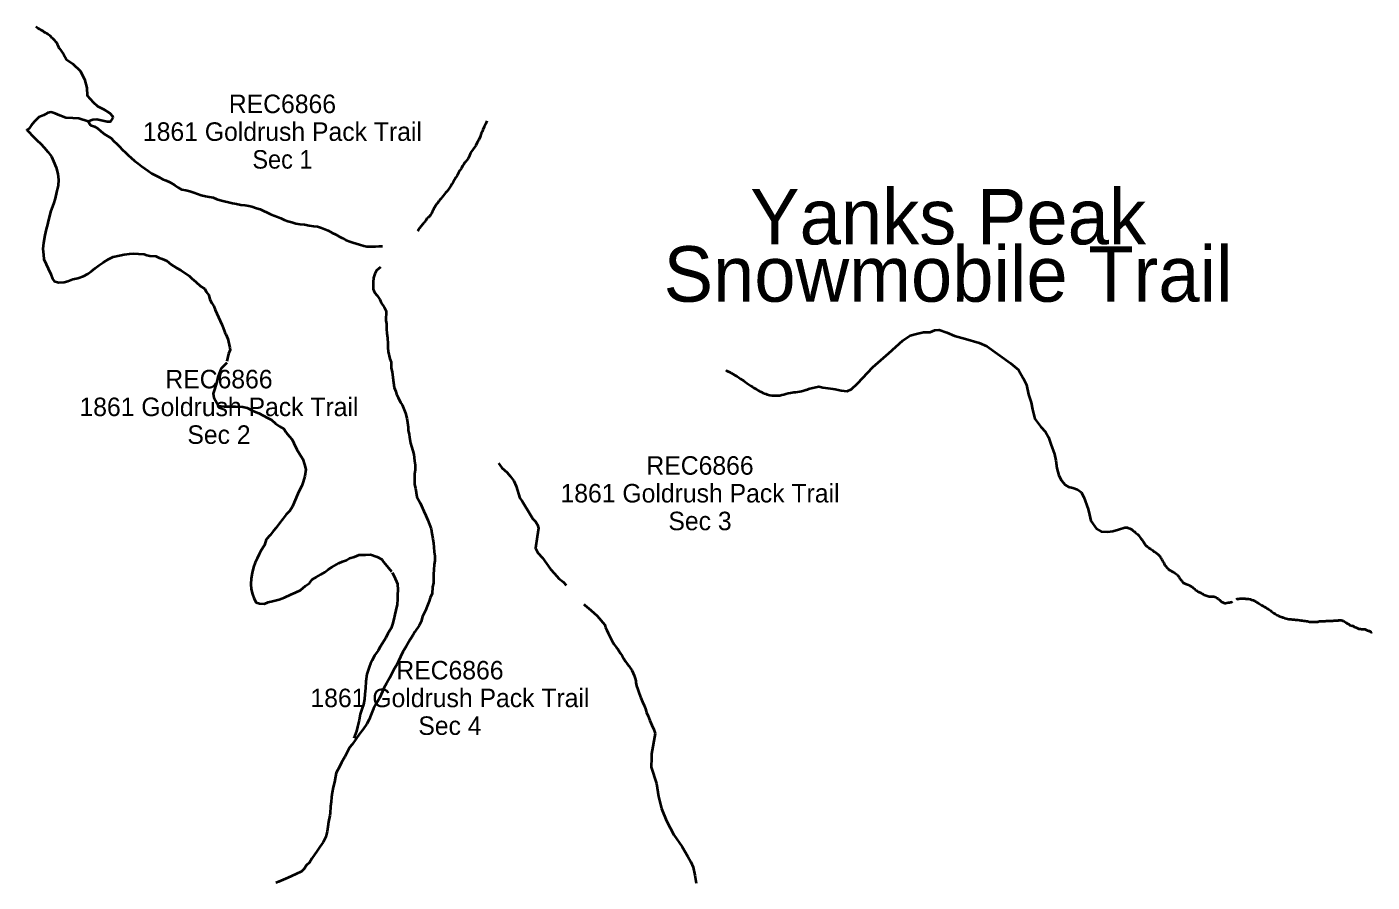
# Model space of a CAD drawing. Extents: x 322505 to 642419, y 5806860 to 5919753.
# Drawn here: x 597056 to 604330, y 5876927 to 5881551 of the extents above; entities that cross this region are included whole.
import ezdxf
from ezdxf.enums import TextEntityAlignment as Align

# ---------------------------------------------------------------- set-up
doc = ezdxf.new("R2010")
doc.units = 0
doc.header["$LTSCALE"] = 140
doc.layers.add('4', color=7, linetype='Continuous', lineweight=40)
doc.layers.add('5', color=7, linetype='Continuous', lineweight=40)

msp = doc.modelspace()

# ---------------------------------------------------------------- linework, layer by layer
at = {"layer": '4'}
for points in [[(599543.3, 5881042.4), (599537, 5881028), (599537, 5881027), (599529, 5881011), (599522, 5880994), (599517, 5880983)], [(599543.3, 5881042.4), (599537, 5881028), (599537, 5881027), (599529, 5881011), (599522, 5880994), (599517, 5880983)], [(599517, 5880983), (599513, 5880974), (599506, 5880957), (599499, 5880940), (599491, 5880925), (599484, 5880910), (599454, 5880870)], [(599517, 5880983), (599513, 5880974), (599506, 5880957), (599499, 5880940), (599491, 5880925), (599484, 5880910), (599454, 5880870)], [(599454, 5880870), (599447, 5880850), (599441, 5880840), (599434, 5880831), (599429, 5880823), (599424, 5880817), (599419, 5880809), (599412, 5880799), (599405, 5880787), (599397, 5880774), (599390, 5880761), (599382, 5880748), (599375, 5880736), (599368, 5880723), (599361, 5880712), (599354, 5880701), (599348, 5880691), (599340, 5880680), (599333, 5880670), (599326, 5880661), (599320, 5880653), (599314, 5880646), (599307, 5880637), (599300, 5880628), (599292, 5880619), (599284, 5880609), (599277, 5880600), (599271, 5880592), (599265, 5880583), (599260, 5880575), (599255, 5880566), (599252, 5880559), (599248, 5880550), (599243, 5880542), (599239, 5880534), (599235, 5880528), (599232, 5880525), (599230, 5880523), (599226, 5880520), (599223, 5880517), (599219, 5880515)], [(599454, 5880870), (599447, 5880850), (599441, 5880840), (599434, 5880831), (599429, 5880823), (599424, 5880817), (599419, 5880809), (599412, 5880799), (599405, 5880787), (599397, 5880774), (599390, 5880761), (599382, 5880748), (599375, 5880736), (599368, 5880723), (599361, 5880712), (599354, 5880701), (599348, 5880691), (599340, 5880680), (599333, 5880670), (599326, 5880661), (599320, 5880653), (599314, 5880646), (599307, 5880637), (599300, 5880628), (599292, 5880619), (599284, 5880609), (599277, 5880600), (599271, 5880592), (599265, 5880583), (599260, 5880575), (599255, 5880566), (599252, 5880559), (599248, 5880550), (599243, 5880542), (599239, 5880534), (599235, 5880528), (599232, 5880525), (599230, 5880523), (599226, 5880520), (599223, 5880517), (599219, 5880515)], [(599219, 5880515), (599217, 5880511), (599215, 5880508), (599213, 5880504), (599211, 5880501), (599208, 5880499), (599205, 5880494), (599200, 5880489), (599196, 5880484), (599192, 5880479), (599188, 5880474), (599184, 5880469), (599181, 5880465), (599177, 5880460), (599173, 5880455), (599169, 5880448), (599167.3, 5880445.9)], [(599219, 5880515), (599217, 5880511), (599215, 5880508), (599213, 5880504), (599211, 5880501), (599208, 5880499), (599205, 5880494), (599200, 5880489), (599196, 5880484), (599192, 5880479), (599188, 5880474), (599184, 5880469), (599181, 5880465), (599177, 5880460), (599173, 5880455), (599169, 5880448), (599167.3, 5880445.9)], [(598968.2, 5880252.5), (598946.2, 5880234.4), (598937.3, 5880216), (598930.3, 5880193.6), (598928.5, 5880171.2), (598927.4, 5880139.5), (598928.5, 5880132.2), (598934.7, 5880115.5), (598950.5, 5880098.3), (598963.4, 5880077), (598972.2, 5880058.8), (598988.1, 5880036), (598988.1, 5880036), (598995.4, 5880021.3), (598997.5, 5880013), (598996.4, 5879963), (598996.4, 5879963), (598999.6, 5879945), (598999.6, 5879934.5), (598999.6, 5879916.7), (599001.7, 5879894.8), (599004.9, 5879869.7), (599008.2, 5879836.6), (599008, 5879815.3), (599010.1, 5879795.1), (599018.5, 5879756.4), (599024.7, 5879737.6), (599024.7, 5879716.7), (599025.8, 5879705.2), (599030, 5879685.3), (599035.2, 5879655), (599042.5, 5879601.6), (599049.8, 5879579.7), (599055.1, 5879565), (599063.4, 5879547.2), (599076, 5879520), (599084.9, 5879507.5), (599084.9, 5879507.5), (599091.7, 5879489.7), (599103.1, 5879462), (599109.5, 5879434.8), (599113.7, 5879412.8), (599117.9, 5879387.2), (599117.9, 5879370.5), (599123.1, 5879346.9), (599124.1, 5879332.3), (599130.4, 5879300.1), (599134.6, 5879281.3), (599141.9, 5879258.3), (599147.2, 5879238.4), (599151.3, 5879204.9), (599155.5, 5879183), (599154.5, 5879155.8), (599151.3, 5879131.7), (599152.4, 5879103.5), (599152.4, 5879077.3), (599156.6, 5879057.5), (599164.9, 5879010.4), (599181.7, 5878978), (599189.8, 5878961.2), (599201.8, 5878931.9), (599213.7, 5878909.1), (599223.6, 5878883.8), (599232.4, 5878860.5), (599241.3, 5878836.2), (599246.1, 5878812.4), (599249.9, 5878783.4), (599254.7, 5878760.1), (599256.9, 5878737.8), (599258.6, 5878713.4), (599260.9, 5878691.6), (599261.6, 5878664.1), (599257.8, 5878644.8), (599255.7, 5878615.5), (599254.7, 5878592.5), (599253.6, 5878574.7), (599253.6, 5878544.4), (599248.1, 5878522.5), (599246.7, 5878487.2), (599237.2, 5878464.2), (599230.4, 5878446.6), (599221, 5878419.4), (599211.5, 5878396.4), (599195.2, 5878363.8), (599188.4, 5878336.7), (599177.5, 5878313.7), (599153.1, 5878281.1), (599143.6, 5878264.9), (599128.7, 5878239.1), (599107, 5878201.1), (599089.4, 5878171.3), (599075.8, 5878144.2), (599065, 5878122.5), (599058.2, 5878106.2), (599040.5, 5878076.4), (599016.1, 5878028.9), (598999.8, 5878001.8), (598987.6, 5877978.8), (598978.1, 5877958.4), (598962.7, 5877922.3), (598946.7, 5877895.2)], [(599605.4, 5879192.5), (599615.4, 5879178.8), (599623.8, 5879166.4), (599637.4, 5879153.5), (599652.1, 5879140.9), (599668.8, 5879121.8), (599689.2, 5879097.1), (599701.7, 5879068), (599720.8, 5879002.9), (599733, 5878986.5), (599750.6, 5878959.5), (599764.2, 5878936.4), (599791.8, 5878890.5), (599806.8, 5878876.4), (599817.2, 5878858.4), (599821.7, 5878841.4), (599815.5, 5878793.3), (599806.2, 5878732.6), (599818.8, 5878708), (599843.6, 5878680.8), (599887.4, 5878618.6), (599908.1, 5878595.7), (599932.8, 5878567.9), (599956, 5878550.5), (599971.3, 5878533)], [(600067.9, 5878429.4), (600073.2, 5878423.8), (600106, 5878396.8), (600139.5, 5878367.4), (600180, 5878318), (600185, 5878304), (600191, 5878290), (600198, 5878273), (600209, 5878251), (600221, 5878230), (600232, 5878212), (600242, 5878197), (600251, 5878186), (600257, 5878177), (600265, 5878164), (600274, 5878150), (600284, 5878134), (600293, 5878120), (600301, 5878108), (600310, 5878097), (600318, 5878086), (600326, 5878073), (600334, 5878057), (600340, 5878045), (600344, 5878033), (600346, 5878023), (600348, 5878014), (600349, 5878006), (600353, 5877989), (600359, 5877968), (600367, 5877946), (600376, 5877923), (600385, 5877901), (600393, 5877882), (600400, 5877864), (600407, 5877845), (600415, 5877825), (600425, 5877801), (600435, 5877775), (600445, 5877752), (600453, 5877731)], [(598946.7, 5877895.2), (598929.7, 5877866.6), (598915.3, 5877829.9), (598906.6, 5877806), (598893.8, 5877783.5), (598874.8, 5877753.3), (598854.2, 5877728.8), (598814.4, 5877670.4), (598800.8, 5877655.1), (598790.8, 5877637.1), (598775.2, 5877603.9), (598757.5, 5877574.3), (598747.2, 5877554.4), (598728, 5877518.2), (598724.5, 5877497.9), (598719.8, 5877466.9), (598711.4, 5877439.7), (598706.7, 5877411.5), (598702.9, 5877387.1), (598700.1, 5877360.8), (598698.2, 5877335.4), (598696.3, 5877300.7), (598693.5, 5877286.6), (598686.6, 5877253.8), (598683.8, 5877225.8), (598679.9, 5877200.9), (598671.6, 5877171.9), (598657.6, 5877142.3), (598640, 5877117.7), (598624.4, 5877096.8), (598596.9, 5877054.9), (598583.8, 5877033.4), (598566.7, 5877018), (598554.4, 5876999.1), (598540.7, 5876985.3), (598510.4, 5876969.8), (598467.5, 5876951), (598416.2, 5876929), (598402.6, 5876922.8)], [(600453, 5877731), (600433.1, 5877620.4), (600433.6, 5877599.9), (600431.6, 5877549.2), (600460.8, 5877460.2), (600471.7, 5877390.4), (600487.8, 5877324.3), (600514.8, 5877257.8), (600553.5, 5877182.2), (600599.4, 5877118.8), (600629.7, 5877065.1), (600645.8, 5877037.6), (600658, 5877007.1), (600666.8, 5876964), (600675, 5876920.9)]]:
    msp.add_lwpolyline(points, dxfattribs=at)
at = {"layer": '5'}
for points in [[(597231.7, 5881433), (597254.4, 5881402.8), (597270.1, 5881374.7), (597303.8, 5881350), (597343.1, 5881312.9), (597367.8, 5881268), (597379, 5881220.9), (597381.3, 5881179.3), (597413.9, 5881144.5), (597437.4, 5881122), (597470, 5881105.2), (597504.8, 5881083.9), (597518.3, 5881068.1), (597519.6, 5881059.4)], [(597519.6, 5881059.4), (597505.6, 5881037), (597488.9, 5881037), (597434.4, 5881050.3), (597412.7, 5881048.9), (597386.9, 5881038.4), (597337.2, 5881054.5), (597304.4, 5881058), (597266, 5881059.4), (597234.5, 5881071.3), (597208, 5881083.1), (597187, 5881089.4), (597169.5, 5881085.2), (597146.5, 5881074), (597120.6, 5881062.2), (597095.5, 5881037), (597078, 5881017.5), (597067.5, 5881002.1), (597055.6, 5880993.7), (597058.4, 5880990.2), (597093.4, 5880953.9), (597110.1, 5880937.8), (597131.1, 5880919), (597148.6, 5880899.4), (597168.1, 5880874.9), (597188, 5880850.7), (597200.2, 5880824.3), (597213.6, 5880790.9), (597222.5, 5880756.4), (597226.1, 5880723.2), (597224.7, 5880692.7), (597216, 5880657.4), (597208.4, 5880623.6), (597200.3, 5880593.2), (597190.5, 5880570.9), (597182.8, 5880549.9), (597174.4, 5880513.6), (597170.9, 5880499.6), (597166.4, 5880481.5), (597159.4, 5880456.3), (597152.4, 5880424.2), (597144.5, 5880383), (597141.8, 5880351.3), (597144.5, 5880318.6), (597148, 5880294.1), (597159.8, 5880268.3), (597170.7, 5880244.9), (597184.4, 5880213), (597193.3, 5880188), (597202.4, 5880176.1), (597225.7, 5880169.3), (597256.9, 5880170.5), (597277.1, 5880176.8), (597304.4, 5880186.3), (597331.2, 5880192.6), (597361.9, 5880203.6), (597385.6, 5880215.2), (597405, 5880230.5), (597425.2, 5880246), (597445.7, 5880261.6), (597468.3, 5880276.8), (597496.2, 5880294.7), (597522.9, 5880308.1), (597556.7, 5880314.2), (597582.4, 5880320.1), (597609.8, 5880323.5), (597633.7, 5880324.7), (597659.5, 5880322.9), (597689, 5880322.7), (597704.4, 5880317.3), (597721.2, 5880313.1), (597752, 5880311.7), (597770.8, 5880301.9), (597787.6, 5880296.3), (597811.4, 5880285.2), (597835.1, 5880265.6), (597864.5, 5880248.8), (597888.2, 5880236.2), (597933.5, 5880204.8), (597947.9, 5880189.7), (597968.4, 5880172.5), (597995.2, 5880149.7), (598018.2, 5880133.8), (598025.2, 5880117.5), (598039.2, 5880099.7), (598044.7, 5880077.3), (598055.1, 5880057.8)], [(597386.9, 5881038.4), (597400.1, 5881019.6), (597400.1, 5881019.6), (597420.7, 5881012.1), (597439.4, 5881000.9), (597456.2, 5880986), (597474.9, 5880971), (597493.6, 5880959.8), (597510.5, 5880948.6), (597510.5, 5880948.6), (597525.4, 5880933.6), (597542.3, 5880918.6), (597557.2, 5880903.7), (597572.2, 5880886.8), (597589, 5880871.9), (597604, 5880856.9), (597619, 5880842), (597637.7, 5880827), (597656.4, 5880812), (597675.1, 5880797.1), (597693.8, 5880785.9), (597710.6, 5880772.8), (597731.2, 5880757.8), (597749.9, 5880748.5), (597770.5, 5880739.1), (597789.2, 5880727.9), (597807.9, 5880720.4), (597828.5, 5880711.1), (597854.7, 5880694.2), (597873.4, 5880683), (597892.1, 5880671.8), (597892.1, 5880671.8), (597914.5, 5880668), (597937, 5880662.4), (597957.5, 5880655), (597978.1, 5880647.5), (597998.7, 5880640), (597998.7, 5880640), (598021.1, 5880636.3), (598041.7, 5880632.5), (598063.4, 5880627.4), (598083, 5880619.6), (598100.8, 5880613.7), (598122.2, 5880608.2), (598146.5, 5880602.6), (598167.1, 5880597), (598189.5, 5880593.2), (598211.9, 5880589.5), (598234.4, 5880587.6), (598255, 5880583.9), (598255, 5880583.9), (598271.9, 5880579.2), (598297.5, 5880571.4), (598316.2, 5880564.5), (598335.4, 5880555.8), (598354.1, 5880546.5), (598372.8, 5880539), (598391.5, 5880531.5), (598410.2, 5880524), (598428.9, 5880516.6), (598447.6, 5880507.2), (598466.3, 5880499.7), (598488.8, 5880494.1), (598509.4, 5880488.5), (598531.8, 5880484.8), (598556.1, 5880482.9), (598582.3, 5880477.3), (598604.8, 5880473.6), (598627.2, 5880471.7), (598627.2, 5880471.7), (598647.8, 5880464.2), (598666.5, 5880456.7), (598685.2, 5880449.2), (598705.8, 5880438), (598705.8, 5880438), (598726.4, 5880428.7), (598745.1, 5880417.4), (598762.5, 5880408.1), (598779.3, 5880400.2), (598797, 5880392.4), (598817.6, 5880384.5), (598854, 5880373.7), (598877.6, 5880366.8), (598894.4, 5880363.9), (598913.5, 5880363.8), (598940.1, 5880364.2), (598959.6, 5880364.9), (598978.3, 5880365.4)], [(598055.1, 5880057.8), (598067, 5880040.2), (598067, 5880040.2), (598074.3, 5880020.3), (598083.3, 5880001.2), (598091.5, 5879982.1), (598100.6, 5879962.2), (598109.7, 5879942.2), (598117.8, 5879923.1), (598123.8, 5879903.4), (598125.4, 5879899.3)], [(598125.4, 5879899.3), (598131.4, 5879888.7), (598142.6, 5879864.9), (598153.8, 5879815.7), (598155.1, 5879804.2), (598146.2, 5879783.2), (598137, 5879743.4)], [(600835, 5879694), (600840, 5879692), (600847, 5879688), (600854, 5879685), (600860, 5879682), (600866, 5879678), (600874, 5879673), (600884, 5879668), (600895, 5879662), (600905, 5879655), (600915, 5879648), (600924, 5879643), (600932, 5879637), (600940, 5879631), (600949, 5879625), (600960, 5879618), (600970, 5879611), (600979, 5879605), (600987, 5879600), (600994, 5879595), (601002, 5879590), (601009, 5879586), (601018, 5879582), (601027, 5879578), (601036, 5879573), (601045, 5879569), (601052, 5879566), (601059, 5879563), (601066, 5879561), (601074, 5879559), (601084, 5879558), (601095, 5879558), (601105, 5879557), (601113, 5879557), (601121, 5879558), (601128, 5879558), (601138, 5879561), (601149, 5879563), (601160, 5879567), (601172, 5879570), (601184, 5879573), (601194, 5879574), (601203, 5879575), (601214, 5879576), (601224, 5879578), (601236, 5879580), (601244, 5879581), (601251, 5879583), (601257, 5879585), (601263, 5879587), (601269, 5879589), (601273, 5879590), (601276, 5879591), (601280, 5879592), (601284, 5879594), (601289, 5879596), (601339, 5879606), (601360, 5879602), (601414, 5879594), (601426, 5879592), (601458, 5879585), (601492, 5879581), (601514, 5879592), (601548, 5879623), (601631, 5879711), (601717, 5879786), (601793, 5879855), (601832, 5879882), (601866, 5879892), (601904, 5879901), (601941, 5879901), (601965, 5879911), (601988, 5879913), (602031, 5879899), (602072, 5879880), (602132, 5879865), (602206, 5879843), (602247, 5879825), (602374, 5879732), (602417, 5879696), (602443, 5879651), (602462, 5879615), (602472, 5879563), (602486, 5879520), (602493, 5879482), (602507, 5879431), (602539, 5879388), (602564, 5879361), (602580, 5879332), (602592, 5879294), (602612, 5879240), (602620, 5879207), (602625, 5879165), (602636, 5879126), (602650, 5879099), (602671, 5879075), (602689, 5879064), (602712, 5879058), (602737, 5879049), (602757, 5879036), (602771, 5879008)], [(598137, 5879735), (598127.2, 5879725.2), (598110.4, 5879707.1), (598100.6, 5879691.7), (598088.1, 5879656.8), (598082.5, 5879631.6), (598072.7, 5879595.3), (598063.6, 5879568.8), (598067, 5879547.6), (598074.6, 5879530.8), (598090.9, 5879502.4), (598121.6, 5879498.2), (598144, 5879498.2), (598184.5, 5879498.2), (598223.6, 5879496.8), (598246, 5879491.2), (598278.1, 5879475.8), (598310.3, 5879463.2), (598332.6, 5879449.3), (598356.4, 5879436.7), (598378.8, 5879425.5), (598399.7, 5879406), (598423.5, 5879390.6), (598444.4, 5879377.3), (598458.4, 5879357.8), (598473.8, 5879338.2), (598489.2, 5879320), (598498.9, 5879300.5), (598515.7, 5879265.5), (598529.7, 5879241.8), (598547.9, 5879213.8), (598556.2, 5879184.5), (598563.2, 5879158.1), (598559.3, 5879122), (598549, 5879090.7), (598541.8, 5879070), (598523.7, 5879035.6), (598511.4, 5879003.8), (598500.3, 5878979.1), (598491.1, 5878958.6), (598476.9, 5878934.8), (598458.4, 5878914.1), (598441.6, 5878893.2), (598420.7, 5878868), (598401.1, 5878841.5), (598388.5, 5878826.1), (598370.4, 5878802.4), (598349.4, 5878778.6), (598339.6, 5878749.1), (598320.8, 5878718.6), (598312, 5878700.2), (598300.4, 5878677), (598289.3, 5878655.7), (598280.3, 5878630.5), (598273.2, 5878600), (598268.6, 5878567.9), (598266.9, 5878538.1), (598269.1, 5878510.2), (598275.1, 5878483.2), (598283.9, 5878458.5), (598295.3, 5878438.7), (598313, 5878432.6), (598341, 5878432.1), (598360.6, 5878440.5), (598382.9, 5878446.1), (598419.3, 5878455.9), (598448.6, 5878465.7), (598483.6, 5878482.4), (598508, 5878493.6), (598534.6, 5878504.8), (598562.5, 5878528.5), (598583.5, 5878542.5), (598599, 5878563.3), (598620, 5878575.3), (598645, 5878590), (598665.9, 5878602.6), (598685.5, 5878616.5), (598703.7, 5878629.1), (598742, 5878652.2), (598762.2, 5878661), (598783.3, 5878668.2), (598800.1, 5878678), (598826.7, 5878686.4), (598851.8, 5878696.2), (598886.8, 5878696.2), (598913.3, 5878697.6), (598949.9, 5878686.5), (598976.5, 5878670.6), (598984.6, 5878658.5), (599011.1, 5878626.7), (599027.9, 5878605.7)], [(602771, 5879008), (602795, 5878943), (602801, 5878913), (602809, 5878880), (602840, 5878837), (602865, 5878823), (602901, 5878820), (602928, 5878824), (602959, 5878833), (602992, 5878845), (602999, 5878845), (603006, 5878845), (603010, 5878843), (603015, 5878841), (603020, 5878839), (603024, 5878837), (603027, 5878835), (603030, 5878833), (603034, 5878830), (603038, 5878827), (603043, 5878823), (603047, 5878820), (603051, 5878816), (603056, 5878812), (603061, 5878808), (603066, 5878803), (603070, 5878798), (603076, 5878791), (603080, 5878785), (603084, 5878780), (603087, 5878776), (603090, 5878771), (603093, 5878767), (603095, 5878763), (603097, 5878760), (603100, 5878756), (603102, 5878753), (603105, 5878749), (603109, 5878746), (603112, 5878743), (603116, 5878740), (603120, 5878737), (603125, 5878733), (603131, 5878729), (603137, 5878725), (603142, 5878721), (603146, 5878718), (603150, 5878715), (603155, 5878712), (603160, 5878709), (603165, 5878705), (603171, 5878701), (603175, 5878697), (603179, 5878693), (603182, 5878689), (603184, 5878685), (603187, 5878681), (603190, 5878676), (603193, 5878672), (603195, 5878667), (603197, 5878663), (603199, 5878660), (603203, 5878653), (603206, 5878647), (603210, 5878641), (603214, 5878635), (603219, 5878629), (603221, 5878626), (603226, 5878621), (603229, 5878619), (603232, 5878616), (603236, 5878613), (603241, 5878611), (603245, 5878608), (603249, 5878606), (603252, 5878605), (603257, 5878603), (603262, 5878600), (603267, 5878596), (603273, 5878592), (603277, 5878588), (603280, 5878584), (603283, 5878581), (603285, 5878577), (603288, 5878573), (603291, 5878568), (603294, 5878564), (603297, 5878559), (603301, 5878555), (603304, 5878552), (603306, 5878549), (603309, 5878546), (603313, 5878544), (603317, 5878542), (603321, 5878540), (603326, 5878538), (603332, 5878536), (603337, 5878534), (603342, 5878532), (603347, 5878529), (603353, 5878526)], [(599030.7, 5878600.1), (599041.9, 5878582), (599059.2, 5878539.4), (599061.6, 5878505.8), (599059.7, 5878481.9), (599059.5, 5878456), (599057.6, 5878428.5), (599051, 5878397.5), (599045.2, 5878373.1), (599039.8, 5878348.1), (599033.2, 5878322.4), (599025.1, 5878300.1), (599008.3, 5878271.4), (598997.2, 5878248), (598979, 5878218.7), (598966.4, 5878199.1), (598955.2, 5878179.6), (598935.7, 5878153), (598923.1, 5878125.1), (598914.5, 5878109.1), (598907.7, 5878094.3), (598894.2, 5878051.1), (598888, 5878011.4), (598886.2, 5877975), (598882.5, 5877942.8), (598880.7, 5877915.5), (598875.7, 5877887.9), (598866.7, 5877861.7), (598858.5, 5877835.3), (598852.3, 5877803.2), (598843.2, 5877766), (598838.8, 5877743.8), (598823.9, 5877704.5)], [(603353, 5878526), (603359, 5878521), (603365, 5878517), (603370, 5878512), (603374, 5878508), (603378, 5878505), (603383, 5878502), (603388, 5878499), (603395, 5878495), (603401, 5878492), (603408, 5878489), (603412, 5878486), (603417, 5878483), (603421, 5878480), (603427, 5878478), (603433, 5878476), (603439, 5878474), (603444, 5878473), (603449, 5878472), (603453, 5878471), (603458, 5878471), (603462, 5878472), (603466, 5878472), (603470, 5878472), (603475, 5878471), (603480, 5878469), (603485, 5878467), (603490, 5878464), (603493, 5878462), (603497, 5878460), (603500, 5878457), (603504, 5878454), (603508, 5878450), (603512, 5878446), (603516, 5878443), (603521, 5878440), (603525, 5878438), (603529, 5878437), (603533, 5878436), (603538, 5878436), (603545, 5878437), (603552, 5878438), (603558, 5878438), (603564, 5878440), (603569, 5878441), (603576, 5878444)], [(603596, 5878455), (603599, 5878456), (603603, 5878458), (603609, 5878459), (603614, 5878460), (603620, 5878461), (603627, 5878461), (603633, 5878461), (603638, 5878460), (603643, 5878460), (603647, 5878459), (603654, 5878459), (603662, 5878458), (603670, 5878456), (603678, 5878454), (603686, 5878452), (603690, 5878450), (603695, 5878448), (603699, 5878445), (603704, 5878442), (603709, 5878439), (603716, 5878435), (603722, 5878431), (603727, 5878428), (603732, 5878425), (603736, 5878422), (603742, 5878419), (603749, 5878415), (603756, 5878411), (603763, 5878407), (603769, 5878403), (603775, 5878399), (603780, 5878395), (603786, 5878391), (603792, 5878387), (603799, 5878382), (603806, 5878378), (603812, 5878374), (603817, 5878371), (603823, 5878368), (603828, 5878365), (603833, 5878363), (603838, 5878362), (603843, 5878360), (603848, 5878358), (603853, 5878357), (603859, 5878355), (603866, 5878353), (603872, 5878351), (603879, 5878349), (603887, 5878348), (603892, 5878348), (603897, 5878347), (603902, 5878347), (603907, 5878347), (603911, 5878347), (603916, 5878346), (603920, 5878346), (603924, 5878346), (603928, 5878345), (603937, 5878344), (603942, 5878343), (603947, 5878342), (603954, 5878341), (603961, 5878340), (603968, 5878339), (603975, 5878338), (603980, 5878337), (603986, 5878336), (603992, 5878335), (603999, 5878335), (604006, 5878335), (604013, 5878335), (604020, 5878335), (604026, 5878335), (604031, 5878335), (604036, 5878335), (604041, 5878336), (604046, 5878337), (604053, 5878337), (604060, 5878338), (604066, 5878338), (604071, 5878338), (604076, 5878338), (604081, 5878339), (604087, 5878339), (604093, 5878339), (604099, 5878340), (604105, 5878340), (604111, 5878340), (604117, 5878340), (604123, 5878341), (604130, 5878341), (604137, 5878341), (604142, 5878341), (604146, 5878342)], [(604146, 5878342), (604151, 5878343), (604156, 5878343), (604162, 5878343), (604168, 5878341), (604172, 5878340), (604175, 5878339), (604178, 5878337), (604183, 5878335), (604188, 5878331), (604191, 5878329), (604195, 5878326), (604200, 5878323), (604204, 5878321), (604210, 5878317), (604216, 5878315), (604219, 5878314), (604222, 5878313), (604225, 5878312), (604229, 5878310), (604233, 5878308), (604239, 5878306), (604244, 5878303), (604248, 5878301), (604251, 5878300), (604255, 5878298), (604259, 5878297), (604263, 5878296), (604267, 5878296), (604272, 5878295), (604277, 5878295), (604284, 5878295), (604287, 5878294), (604291, 5878294), (604295, 5878292), (604301, 5878290), (604306, 5878288), (604310, 5878286), (604314, 5878285), (604318, 5878283), (604322, 5878281), (604326, 5878279), (604330, 5878280)]]:
    msp.add_lwpolyline(points, dxfattribs=at)
msp.add_spline([(597231.8, 5881432.8), (597216.7, 5881464.3), (597196.1, 5881487.2), (597175.5, 5881506.1), (597156.5, 5881518.7), (597129.5, 5881534.5), (597103.7, 5881550.5)], degree=3, dxfattribs=at)

# ---------------------------------------------------------------- texts
at = {"layer": '4'}
for s, p in [('REC6866', (598437.4, 5881084.5)), ('REC6866', (598437.4, 5881084.5)), ('1861 Goldrush Pack Trail', (598437.4, 5880934.5)), ('1861 Goldrush Pack Trail', (598437.4, 5880934.5)), ('REC6866', (598094.2, 5879596.5)), ('REC6866', (598094.2, 5879596.5)), ('1861 Goldrush Pack Trail', (598094.2, 5879446.5)), ('1861 Goldrush Pack Trail', (598094.2, 5879446.5)), ('Sec 2', (598094.3, 5879296.5)), ('Sec 2', (598094.3, 5879296.5)), ('REC6866', (600695.6, 5879129.6)), ('1861 Goldrush Pack Trail', (600695.6, 5878979.6)), ('Sec 3', (600695.6, 5878829.6)), ('REC6866', (599343.2, 5878023)), ('1861 Goldrush Pack Trail', (599343.2, 5877873)), ('Sec 4', (599343.2, 5877723))]:
    msp.add_text(s, height=100, dxfattribs=at).set_placement(p, align=Align.CENTER)
at = {"layer": '4', "width": 0.95}
msp.add_text('Sec 1', height=100, dxfattribs=at).set_placement((598437.4, 5880784.5), align=Align.CENTER)
msp.add_text('Sec 1', height=100, dxfattribs=at).set_placement((598437.4, 5880784.5), align=Align.CENTER)
at = {"layer": '5'}
for s, p in [('Yanks Peak', (602036.9, 5880374.9)), ('Snowmobile Trail', (602036.9, 5880064.9))]:
    msp.add_text(s, height=300, dxfattribs=at).set_placement(p, align=Align.CENTER)

doc.saveas('drawing.dxf')
